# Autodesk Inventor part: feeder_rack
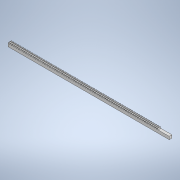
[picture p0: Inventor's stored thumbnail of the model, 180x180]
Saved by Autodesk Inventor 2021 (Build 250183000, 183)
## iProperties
Company: meta-matic.com
Created: 2026-11
Part Number: feeder_rack
Material: Generic
Description: Rack Gear - meta-matic-generator 1.3
Document SubType Name: Modeling
Designer: alolo
Authority: META-MATIC-ID: 3dc0ee3cef1d
Density: 1 g/cm^3
Appearance: Default
Sending System: Open CASCADE
Preprocessor: meta-matic-generator 1.3
Title: Rack Gear_3dc0ee3cef1d
Author: Takahashi Mizuki @tkhsmz
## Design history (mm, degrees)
feature "Base1"
sketch "Sketch1"
  geometry: L1 (10, 10.5)-(0, 10.5) reference; L2 (0, 10.5)-(10, 10.5); L3 (10, 10.5)-(10, 0); L4 (10, 0)-(0, 0); L5 (0, 0)-(0, 10.5); 1 further point
  constraints: 8 end point, 2 parallel, 1 horizontal, 1 perpendicular
extrude "Extrusion1" join sketch "Sketch1" distance "d0" = 40; taper "d1" = 0 deg
body "Solid1"
